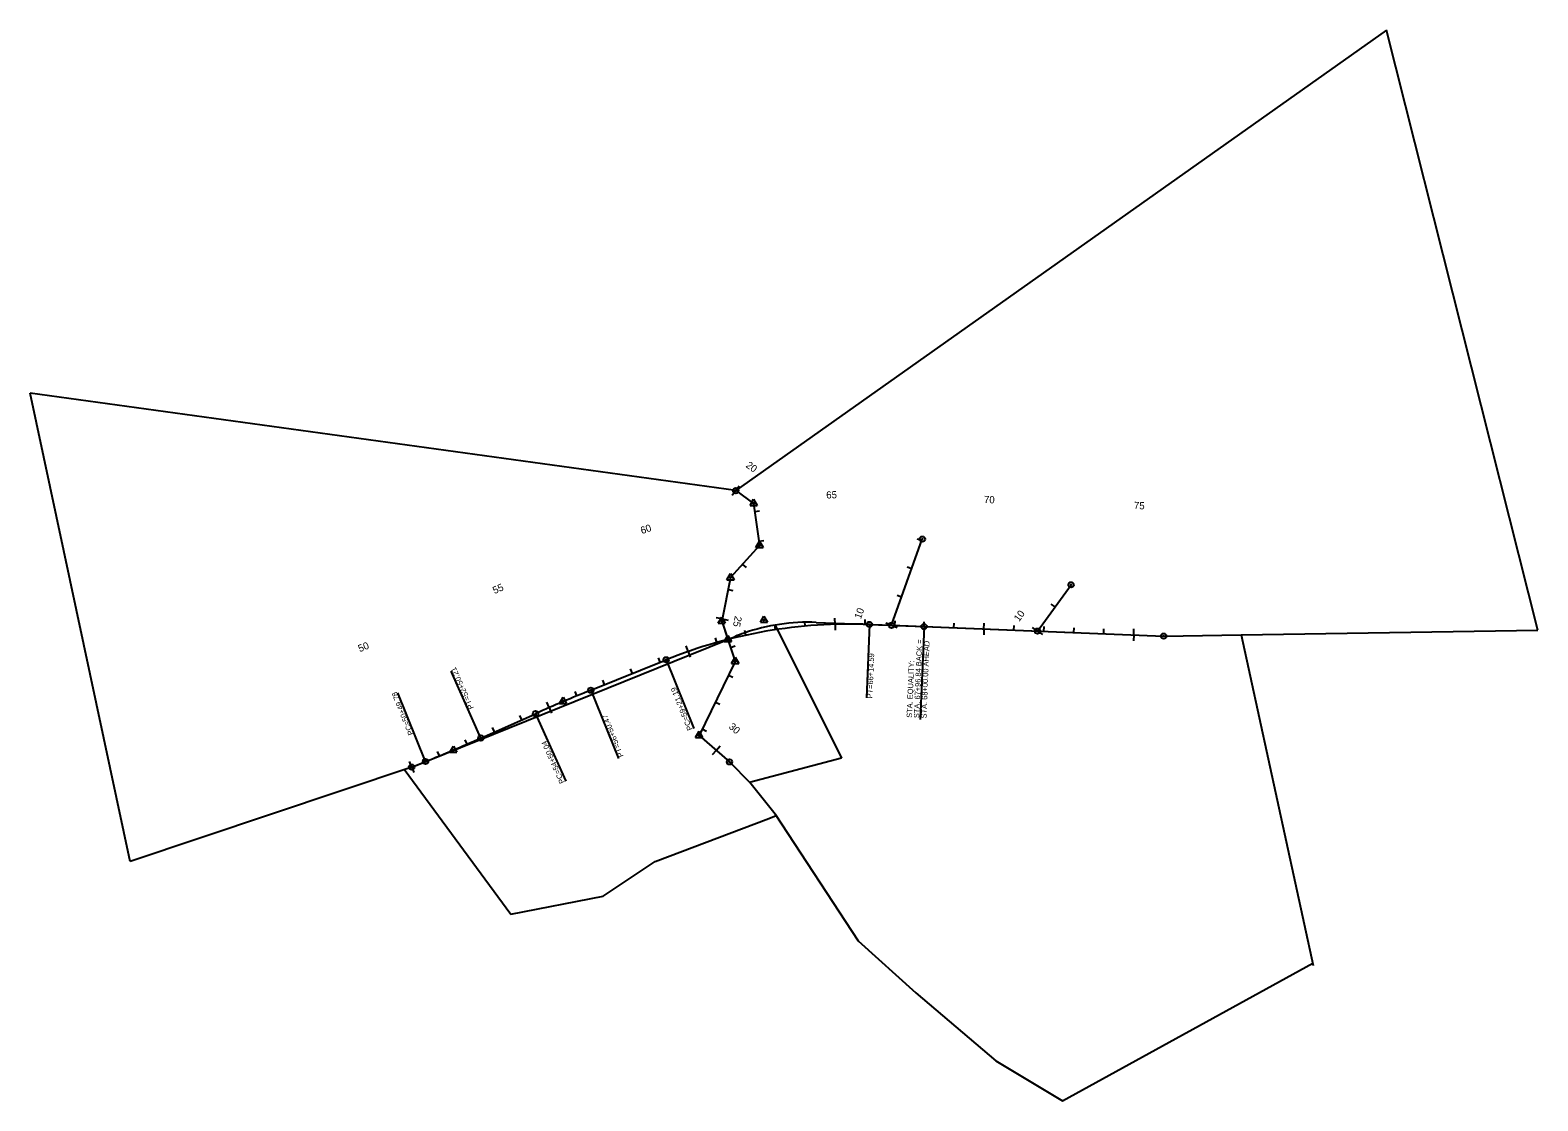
# Model space of a CAD drawing. Extents: x 1965498 to 1970527, y 1116335 to 1119906.
import ezdxf

# ---------------------------------------------------------------- set-up
doc = ezdxf.new("R2010")
doc.units = 0
for name, color, linetype in [('RD_EX_DV_Prop', 7, 'Continuous'), ('RD_HC_CL', 7, 'Continuous'), ('RD_HC_CL_Rel', 7, 'Continuous'), ('RD_HC_Data', 7, 'Continuous'), ('RD_HC_Data_Rel', 7, 'Continuous'), ('RD_HC_Data_Tic_Rel', 7, 'Continuous'), ('RD_HC_TX_Rel_Sta50', 7, 'Continuous'), ('RD_HC_TX_StaOther', 7, 'Continuous'), ('RD_Sketch2', 7, 'Continuous')]:
    doc.layers.add(name, color=color, linetype=linetype)

msp = doc.modelspace()

# ---------------------------------------------------------------- linework, layer by layer
at = {"layer": 'RD_EX_DV_Prop'}
for p, q in [((1970021.7, 1119906.4), (1967851.7, 1118370.2)), ((1970527.1, 1117904.7), (1970021.7, 1119906.4)), ((1965831.2, 1117132.9), (1965498.1, 1118695)), ((1967851.7, 1118370.2), (1965498.1, 1118695)), ((1967851.7, 1118370.2), (1967911.4, 1118327.7)), ((1967911.4, 1118327.7), (1967931.1, 1118187.5)), ((1967931.1, 1118187.5), (1967834, 1118080)), ((1967834, 1118080), (1967804.8, 1117934.9)), ((1967804.8, 1117934.9), (1967825.2, 1117874.1)), ((1967983.3, 1117921.8), (1968204.3, 1117478.1)), ((1968120.3, 1117930.9), (1968371.4, 1117921)), ((1968371.4, 1117921), (1969279, 1117884.9)), ((1969279, 1117884.9), (1969537.8, 1117889)), ((1969537.8, 1117889), (1970527.1, 1117904.7)), ((1969537.8, 1117889), (1969777.4, 1116786.4)), ((1967698.1, 1117822.7), (1967825.2, 1117874.1)), ((1967825.2, 1117874.1), (1967849.5, 1117883.9)), ((1967825.2, 1117874.1), (1967849.8, 1117800.6)), ((1966770.7, 1117448.1), (1967698.1, 1117822.7)), ((1967849.8, 1117800.6), (1967729.3, 1117553.7)), ((1967729.3, 1117553.7), (1967830.8, 1117465.4)), ((1966770.7, 1117448.1), (1965831.2, 1117132.9)), ((1966745.7, 1117440.8), (1967101.3, 1116957.5)), ((1967830.8, 1117465.4), (1967898.1, 1117396.8)), ((1968204.3, 1117478.1), (1967897.6, 1117396.5)), ((1967983, 1117291.4), (1967898.1, 1117396.8)), ((1967962.1, 1117277.1), (1967986.9, 1117286.5)), ((1967983, 1117291.4), (1968260.1, 1116868.2)), ((1967986.9, 1117286.5), (1967983, 1117291.4)), ((1967582.6, 1117133.3), (1967962.1, 1117277.1)), ((1967409.3, 1117017.8), (1967582.6, 1117133.3)), ((1967101.3, 1116957.5), (1967409.3, 1117017.8)), ((1968260.1, 1116868.2), (1968452.8, 1116695.3)), ((1968941.8, 1116334.8), (1969776.6, 1116794.1)), ((1968452.8, 1116695.3), (1968719.5, 1116468.1)), ((1968719.5, 1116468.1), (1968941.8, 1116334.8))]:
    msp.add_line(p, q, dxfattribs=at)
for start, end in [(109.2117, 111.9958), (87.7266, 109.2117)]:
    msp.add_arc((1968094.4, 1117277.5), 653.9, start, end, dxfattribs=at)
at = {"layer": 'RD_HC_CL'}
for p, q in [((1967851.7, 1118370.2), (1967911.4, 1118327.7)), ((1967911.4, 1118327.7), (1967931.1, 1118187.5)), ((1968371.4, 1117921), (1968474, 1118208.6)), ((1967931.1, 1118187.5), (1967834, 1118080)), ((1967834, 1118080), (1967804.8, 1117934.9)), ((1968858.2, 1117901.7), (1968970.1, 1118056.2)), ((1967804.8, 1117934.9), (1967849.8, 1117800.6)), ((1967849.8, 1117800.6), (1967729.3, 1117553.7)), ((1967729.3, 1117553.7), (1967830.8, 1117465.4))]:
    msp.add_line(p, q, dxfattribs=at)
at = {"layer": 'RD_HC_CL_Rel'}
for p, q in [((1968297.5, 1117923.9), (1968479.6, 1117916.7)), ((1968479.6, 1117916.7), (1969279, 1117884.9)), ((1967368.4, 1117704.6), (1967619.4, 1117806)), ((1967001.4, 1117545.1), (1967183.9, 1117626.3)), ((1966770.7, 1117448.1), (1966816.9, 1117466.8))]:
    msp.add_line(p, q, dxfattribs=at)
for centre, radius, start, end in [((1968232.6, 1116288.2), 1637, 87.7266, 111.9958), ((1969514.4, 1112392.1), 5729.6, 111.99584, 114.00015), ((1964670.9, 1122779.3), 5729.6, 291.9959, 294.00015)]:
    msp.add_arc(centre, radius, start, end, dxfattribs=at)
at = {"layer": 'RD_HC_Data'}
for p, q in [((1967851.7, 1118370.2), (1967840.1, 1118354)), ((1967851.7, 1118370.2), (1967863.4, 1118386.5)), ((1967899.5, 1118320.8), (1967911.4, 1118341.4)), ((1967911.4, 1118341.4), (1967923.3, 1118320.8)), ((1967899.5, 1118320.8), (1967923.3, 1118320.8)), ((1967915.1, 1118301.2), (1967930.9, 1118303.4)), ((1967919.1, 1118180.7), (1967931.1, 1118201.3)), ((1967929, 1118202.2), (1967944.8, 1118204.4)), ((1967931.1, 1118201.3), (1967943, 1118180.7)), ((1968472.1, 1118203.5), (1968457.1, 1118208.9)), ((1967919.1, 1118180.7), (1967943, 1118180.7)), ((1967822.1, 1118073.1), (1967834, 1118093.7)), ((1967834, 1118093.7), (1967845.9, 1118073.1)), ((1967874, 1118124.2), (1967885.9, 1118113.5)), ((1968438.5, 1118109.4), (1968423.5, 1118114.7)), ((1967822.1, 1118073.1), (1967845.9, 1118073.1)), ((1967826.1, 1118040.4), (1967841.7, 1118037.2)), ((1968404.9, 1118015.2), (1968389.9, 1118020.5)), ((1968916.8, 1117982.6), (1968903.9, 1117992)), ((1967806.3, 1117942.4), (1967786.7, 1117946.3)), ((1967792.9, 1117928), (1967804.8, 1117948.6)), ((1967804.8, 1117948.6), (1967816.7, 1117928)), ((1967806.3, 1117942.4), (1967825.9, 1117938.4)), ((1967792.9, 1117928), (1967816.7, 1117928)), ((1967813.4, 1117866.9), (1967825.3, 1117887.5)), ((1967825.3, 1117887.5), (1967837.2, 1117866.9)), ((1968371.4, 1117921), (1968352.5, 1117927.7)), ((1968371.4, 1117921), (1968390.2, 1117914.3)), ((1968858.2, 1117901.7), (1968842, 1117913.4)), ((1968858.2, 1117901.7), (1968874.4, 1117889.9)), ((1967813.4, 1117866.9), (1967837.2, 1117866.9)), ((1967834.2, 1117847.3), (1967849.3, 1117852.4)), ((1967837.9, 1117793.7), (1967849.8, 1117814.4)), ((1967837.9, 1117793.7), (1967861.7, 1117793.7)), ((1967849.8, 1117814.4), (1967861.7, 1117793.7)), ((1967827.6, 1117755), (1967841.9, 1117748)), ((1967783.7, 1117665.1), (1967798.1, 1117658.1)), ((1967717.4, 1117546.8), (1967729.3, 1117567.4)), ((1967717.4, 1117546.8), (1967741.2, 1117546.8)), ((1967729.3, 1117567.4), (1967741.2, 1117546.8)), ((1967739.8, 1117575.2), (1967754.2, 1117568.2)), ((1967786.6, 1117503.8), (1967773.5, 1117488.7)), ((1967786.6, 1117503.8), (1967799.8, 1117518.9))]:
    msp.add_line(p, q, dxfattribs=at)
for centre, radius in [((1967851.7, 1118370.2), 9), ((1967851.7, 1118370.2), 0.845), ((1967911.4, 1118327.7), 1.59), ((1967931.1, 1118187.5), 1.59), ((1968474, 1118208.6), 9), ((1968474, 1118208.6), 0.845), ((1967834, 1118080), 1.59), ((1968970.1, 1118056.2), 9), ((1968970.1, 1118056.2), 0.845), ((1967804.8, 1117934.9), 1.59), ((1968371.4, 1117921), 9), ((1968371.4, 1117921), 0.845), ((1968858.2, 1117901.7), 9), ((1968858.2, 1117901.7), 0.845), ((1967825.3, 1117873.7), 1.59), ((1967849.8, 1117800.6), 1.59), ((1967729.3, 1117553.7), 1.59), ((1967830.8, 1117465.4), 9), ((1967830.8, 1117465.4), 0.845)]:
    msp.add_circle(centre, radius, dxfattribs=at)
at = {"layer": 'RD_HC_Data_Rel'}
for p, q in [((1967933.9, 1117931), (1967945.8, 1117951.6)), ((1967945.8, 1117951.6), (1967957.7, 1117931)), ((1967933.9, 1117931), (1967957.7, 1117931)), ((1968297.5, 1117923.9), (1968287.8, 1117678.6)), ((1968479.6, 1117916.7), (1968467.3, 1117606.4)), ((1967619.4, 1117806), (1967712, 1117577)), ((1967001.4, 1117545.1), (1966902.3, 1117767.7)), ((1966816.9, 1117466.8), (1966724.5, 1117695.5)), ((1967368.4, 1117704.6), (1967460.4, 1117477)), ((1967263.6, 1117660.2), (1967275.5, 1117680.9)), ((1967263.6, 1117660.2), (1967287.4, 1117660.2)), ((1967275.5, 1117680.9), (1967287.4, 1117660.2)), ((1967183.9, 1117626.3), (1967284.4, 1117400.7)), ((1966897.9, 1117497.4), (1966909.8, 1117518.1)), ((1966897.9, 1117497.4), (1966921.7, 1117497.4)), ((1966909.8, 1117518.1), (1966921.7, 1117497.4))]:
    msp.add_line(p, q, dxfattribs=at)
for centre, radius in [((1967945.8, 1117937.9), 1.59), ((1968297.5, 1117923.9), 9), ((1968297.5, 1117923.9), 0.845), ((1968479.6, 1117916.7), 9), ((1968479.6, 1117916.7), 0.845), ((1969279, 1117884.9), 9), ((1969279, 1117884.9), 0.845), ((1967619.4, 1117806), 9), ((1967619.4, 1117806), 0.845), ((1967368.4, 1117704.6), 9), ((1967368.4, 1117704.6), 0.845), ((1967183.9, 1117626.3), 9), ((1967275.5, 1117667.1), 1.59), ((1967183.9, 1117626.3), 0.845), ((1967001.4, 1117545.1), 9), ((1967001.4, 1117545.1), 0.845), ((1966909.8, 1117504.3), 1.59), ((1966770.7, 1117448.1), 9), ((1966770.7, 1117448.1), 0.845), ((1966816.9, 1117466.8), 9), ((1966816.9, 1117466.8), 0.845)]:
    msp.add_circle(centre, radius, dxfattribs=at)
at = {"layer": 'RD_HC_Data_Tic_Rel'}
for p, q in [((1968182.9, 1117924.4), (1968182.3, 1117944.4)), ((1968282.9, 1117924.4), (1968283.4, 1117940.4)), ((1967885.6, 1117888), (1967882.2, 1117903.6)), ((1967983.9, 1117906.2), (1967981.5, 1117922)), ((1968083.1, 1117918.4), (1968081.7, 1117934.3)), ((1968182.9, 1117924.4), (1968183.5, 1117904.5)), ((1968382.8, 1117920.5), (1968383.5, 1117936.5)), ((1968479.6, 1117916.7), (1968480.3, 1117932.7)), ((1968579.6, 1117912.7), (1968580.2, 1117928.7)), ((1968679.5, 1117908.7), (1968678.7, 1117888.8)), ((1968679.5, 1117908.7), (1968680.3, 1117928.7)), ((1968779.4, 1117904.8), (1968780, 1117920.8)), ((1968879.3, 1117900.8), (1968880, 1117916.8)), ((1968979.3, 1117896.8), (1968979.9, 1117912.8)), ((1969079.2, 1117892.9), (1969079.8, 1117908.9)), ((1969179.1, 1117888.9), (1969178.3, 1117868.9)), ((1969179.1, 1117888.9), (1969179.9, 1117908.9)), ((1967693.2, 1117833.8), (1967686.6, 1117852.7)), ((1967788.6, 1117863.8), (1967784.2, 1117879.2)), ((1967599.8, 1117798.1), (1967593.8, 1117812.9)), ((1967693.2, 1117833.8), (1967699.8, 1117814.9)), ((1967414.4, 1117723.2), (1967408.4, 1117738)), ((1967507.1, 1117760.7), (1967501.1, 1117775.5)), ((1967321.7, 1117685.5), (1967315.6, 1117700.3)), ((1967229.7, 1117646.5), (1967221.7, 1117664.8)), ((1967229.7, 1117646.5), (1967237.6, 1117628.1)), ((1967138.2, 1117606), (1967131.7, 1117620.6)), ((1966955.4, 1117524.8), (1966949, 1117539.5)), ((1967046.9, 1117565.3), (1967040.4, 1117579.9)), ((1966863.4, 1117485.8), (1966857.3, 1117500.6)), ((1966770.7, 1117448.1), (1966763.2, 1117466.7)), ((1966770.7, 1117448.1), (1966778.2, 1117429.6))]:
    msp.add_line(p, q, dxfattribs=at)
at = {"layer": 'RD_Sketch2'}
msp.add_line((1967183.9, 1117626.3), (1967183.9, 1117626.3), dxfattribs=at)

# ---------------------------------------------------------------- texts
at = {"layer": 'RD_HC_Data_Rel'}
for s, rotation, p in [('STA. 67+96.84 BACK =', 87.7266, (1968463.6, 1117611.2)), ('STA. 68+00.00 AHEAD', 87.7266, (1968487.9, 1117610.2)), ('PT=66+14.59', 87.7266, (1968307.6, 1117676.9)), ('STA. EQUALITY:', 87.7266, (1968439.4, 1117612.1)), ('PT=52+50.21', 114.0002, (1966978.2, 1117645.7)), ('PC=50+49.78', 111.9959, (1966777.6, 1117558.7)), ('PC=59+21.19', 111.9958, (1967708.3, 1117574.4)), ('PT=56+50.47', 111.9958, (1967478.2, 1117485.1)), ('PC=54+50.04', 114.0002, (1967281.8, 1117397.7))]:
    msp.add_text(s, height=18, rotation=rotation, dxfattribs=at).set_placement(p)
at = {"layer": 'RD_HC_TX_Rel_Sta50'}
for s, rotation, p in [('65', 1.7374, (1968153.8, 1118343.8)), ('70', 357.7266, (1968679.3, 1118329.1)), ('75', 357.7266, (1969179.4, 1118309.2)), ('60', 19.2374, (1967538.9, 1118224.8)), ('55', 23.5006, (1967047.1, 1118025.1)), ('50', 21.9959, (1966597.8, 1117831.2))]:
    msp.add_text(s, height=24, rotation=rotation, dxfattribs=at).set_placement(p)
at = {"layer": 'RD_HC_TX_StaOther'}
for s, rotation, p in [('20', 324.4755, (1967883.2, 1118450.2)), ('25', 258.6104, (1967849.1, 1117953.4)), ('10', 70.3698, (1968268.9, 1117940.3)), ('10', 54.0772, (1968796.5, 1117931.2)), ('30', 318.9993, (1967826.3, 1117579.7))]:
    msp.add_text(s, height=24, rotation=rotation, dxfattribs=at).set_placement(p)

doc.saveas('drawing.dxf')
